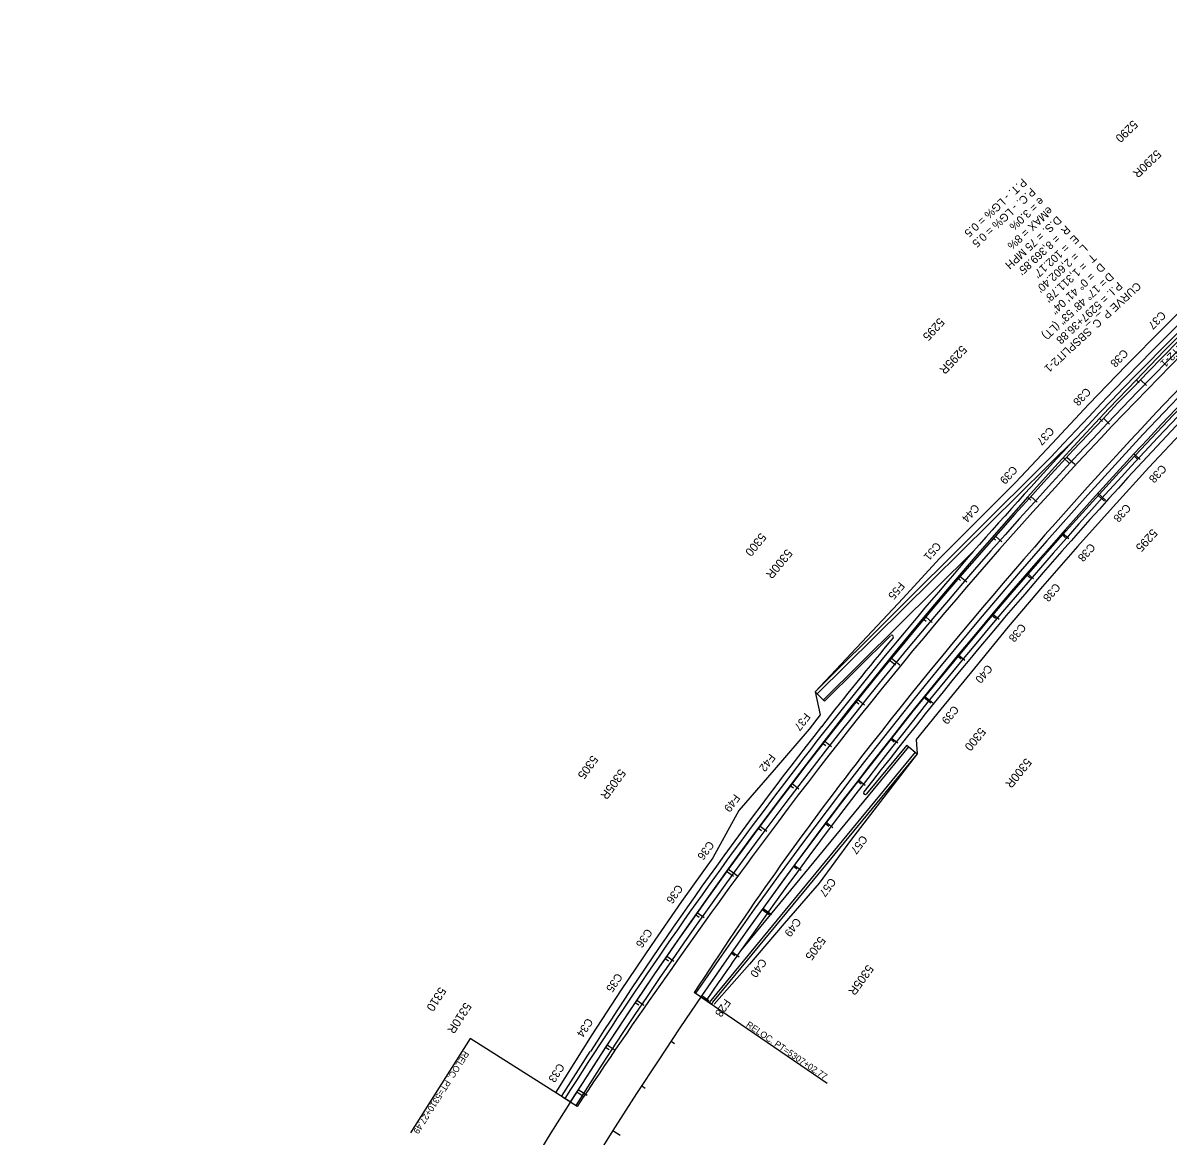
# Model space of a CAD drawing. Extents: x 2160877 to 2175861, y 601747 to 617724.
# Drawn here: x 2161211 to 2163357, y 604108 to 606194 of the extents above; entities that cross this region are included whole.
import ezdxf

# ---------------------------------------------------------------- set-up
doc = ezdxf.new("R2010")
doc.units = 0
for name, color, linetype in [('RD_HC_Cl', 7, 'Continuous'), ('RD_HC_CL_Rel', 7, 'Continuous'), ('RD_HC_Data_Rel', 7, 'Continuous'), ('RD_HC_Data_Tic', 7, 'Continuous'), ('RD_HC_Data_Tic_Rel', 7, 'Continuous'), ('RD_HC_TX_Rel_Sta50', 7, 'Continuous'), ('RD_HC_TX_StaOther', 7, 'Continuous'), ('RD_PD_CstnLmt', 7, 'Continuous'), ('RD_PD_CstnLmt_TX', 7, 'Continuous'), ('RD_PD_Final_LnLine', 7, 'Continuous'), ('RD_PD_Final_TrvlWay', 7, 'Continuous')]:
    doc.layers.add(name, color=color, linetype=linetype)

msp = doc.modelspace()

# ---------------------------------------------------------------- linework, layer by layer
at = {"layer": 'RD_HC_Cl'}
for radius in [8641.9, 8545.9]:
    msp.add_arc((2169535, 599544.7), radius, 132.71947, 164.41949, dxfattribs=at)
at = {"layer": 'RD_HC_CL_Rel'}
for centre, radius, end in [((2169810, 599356.6), 8879.1, 145.62858), ((2169305.2, 599690.4), 8369.8, 147.62243)]:
    msp.add_arc(centre, radius, 129.80773, end, dxfattribs=at)
at = {"layer": 'RD_HC_Data_Rel'}
msp.add_line((2162481.2, 604369.4), (2162717.9, 604207.5), dxfattribs=at)
msp.add_lwpolyline([(2162236.6, 604172.5), (2162048.9, 604291.4), (2161937, 604114.9)], dxfattribs=at)
at = {"layer": 'RD_HC_Data_Tic'}
for p, q in [((2163297.3, 605525.8), (2163303, 605520.3)), ((2163228.5, 605453.3), (2163234.3, 605447.8)), ((2163160.5, 605379.9), (2163172.3, 605369.1)), ((2163293.8, 605382.6), (2163299.6, 605377.1)), ((2163093.4, 605305.7), (2163099.4, 605300.4)), ((2163225.9, 605309.1), (2163237.7, 605298.3)), ((2163027.2, 605230.8), (2163033.2, 605225.6)), ((2163158.9, 605234.9), (2163164.9, 605229.6)), ((2162961.9, 605155.1), (2162967.9, 605149.9)), ((2163092.7, 605159.9), (2163098.8, 605154.7)), ((2162897.4, 605078.7), (2162903.5, 605073.6)), ((2163027.5, 605084.1), (2163033.6, 605079)), ((2162833.8, 605001.5), (2162846.2, 604991.4)), ((2162963.1, 605007.6), (2162969.3, 605002.5)), ((2162771.1, 604923.6), (2162777.4, 604918.6)), ((2162899.6, 604930.3), (2162912.1, 604920.3)), ((2162837.1, 604852.3), (2162843.3, 604847.4)), ((2162709.3, 604845), (2162715.6, 604840.1)), ((2162648.4, 604765.7), (2162654.8, 604760.8)), ((2162775.4, 604773.6), (2162781.8, 604768.7)), ((2162588.5, 604685.6), (2162594.9, 604680.9)), ((2162714.7, 604694.1), (2162721.1, 604689.3)), ((2162654.9, 604614), (2162661.4, 604609.2)), ((2162529.5, 604604.9), (2162542.4, 604595.5)), ((2162596.1, 604533.1), (2162609.1, 604523.8)), ((2162471.4, 604523.5), (2162477.9, 604518.9)), ((2162414.2, 604441.4), (2162420.8, 604436.9)), ((2162538.2, 604451.6), (2162544.7, 604447)), ((2162358.1, 604358.7), (2162364.7, 604354.2)), ((2162481.2, 604369.4), (2162487.8, 604364.9)), ((2162302.8, 604275.3), (2162309.5, 604271)), ((2162425.3, 604286.5), (2162431.9, 604282.1)), ((2162248.6, 604191.3), (2162262.1, 604182.7)), ((2162370.3, 604203), (2162377, 604198.6)), ((2162316.3, 604118.8), (2162329.8, 604110.3))]:
    msp.add_line(p, q, dxfattribs=at)
at = {"layer": 'RD_HC_Data_Tic_Rel'}
for p, q in [((2163305.1, 605525.9), (2163316.6, 605514.8)), ((2163235.8, 605453.8), (2163247.4, 605442.8)), ((2163292.8, 605387), (2163304.6, 605376.1)), ((2163167.4, 605380.9), (2163182.1, 605367.3)), ((2163099.8, 605307.2), (2163111.7, 605296.4)), ((2163225.3, 605313.2), (2163240.2, 605299.8)), ((2163158.7, 605238.7), (2163170.7, 605228.1)), ((2163033.2, 605232.6), (2163045.2, 605222)), ((2162967.4, 605157.3), (2162979.5, 605146.8)), ((2163092.8, 605163.4), (2163104.9, 605152.9)), ((2163027.9, 605087.4), (2163040.1, 605077)), ((2162902.6, 605081.2), (2162914.8, 605070.9)), ((2162838.6, 605004.3), (2162854.1, 604991.6)), ((2162963.8, 605010.6), (2162976.1, 605000.4)), ((2162775.6, 604926.7), (2162788.1, 604916.7)), ((2162900.5, 604933.1), (2162916.1, 604920.6)), ((2162838.2, 604855), (2162850.7, 604845.1)), ((2162713.5, 604848.3), (2162726.1, 604838.4)), ((2162652.3, 604769.2), (2162665.1, 604759.4)), ((2162776.7, 604776.1), (2162789.3, 604766.3)), ((2162592.1, 604689.3), (2162605, 604679.8)), ((2162716.1, 604696.6), (2162728.9, 604686.9)), ((2162656.4, 604616.3), (2162669.3, 604606.9)), ((2162532.9, 604608.7), (2162549.1, 604597)), ((2162474.6, 604527.5), (2162487.7, 604518.2)), ((2162597.6, 604535.4), (2162613.9, 604523.8)), ((2162417.3, 604445.5), (2162430.5, 604436.4)), ((2162539.7, 604453.9), (2162552.8, 604444.7)), ((2162361, 604362.9), (2162374.3, 604354)), ((2162482.8, 604371.7), (2162496, 604362.6)), ((2162305.7, 604279.6), (2162319, 604270.8)), ((2162251.3, 604195.6), (2162268.2, 604184.9))]:
    msp.add_line(p, q, dxfattribs=at)
at = {"layer": 'RD_PD_CstnLmt'}
for p, q in [((2163419.9, 605694.5), (2163348.9, 605623.5)), ((2163348.9, 605623.5), (2163278.1, 605552.2)), ((2163278.1, 605552.2), (2163208.3, 605480)), ((2163208.3, 605480), (2163139.9, 605406.4)), ((2163388.7, 605434), (2163320.6, 605361.3)), ((2163139.9, 605406.4), (2163070.9, 605333.4)), ((2163320.6, 605361.3), (2163253.7, 605287.5)), ((2163070.9, 605333.4), (2162999.9, 605262)), ((2163253.7, 605287.5), (2163187, 605213.6)), ((2162999.9, 605262), (2162928.5, 605190.9)), ((2163187, 605213.6), (2163121.5, 605138.6)), ((2162928.5, 605190.9), (2162860.7, 605116.4)), ((2163121.5, 605138.6), (2163057.1, 605062.7)), ((2162860.7, 605116.4), (2162695.3, 604940.8)), ((2163057.1, 605062.7), (2162994.2, 604985.4)), ((2162994.2, 604985.4), (2162930.9, 604908.6)), ((2162684.3, 604871.1), (2162618.9, 604794.7)), ((2162886.8, 604824.9), (2162761.6, 604662.3)), ((2162618.9, 604794.7), (2162552.6, 604718.7)), ((2162552.6, 604718.7), (2162503.6, 604630)), ((2162761.6, 604662.3), (2162702.7, 604582.3)), ((2162503.6, 604630), (2162445.2, 604548.3)), ((2162702.7, 604582.3), (2162637.1, 604507.1)), ((2162445.2, 604548.3), (2162388, 604465.8)), ((2162637.1, 604507.1), (2162572.7, 604430.8)), ((2162388, 604465.8), (2162332.1, 604382.3)), ((2162572.7, 604430.8), (2162505.9, 604355.8)), ((2162332.1, 604382.3), (2162277.1, 604298.3)), ((2162277.1, 604298.3), (2162209.5, 604191))]:
    msp.add_line(p, q, dxfattribs=at)
for points in [[(2162695.3, 604940.8), (2162705.1, 604897.6), (2162684.3, 604871.1)], [(2162930.9, 604908.6), (2162884.8, 604851.6), (2162886.8, 604824.9)]]:
    msp.add_lwpolyline(points, dxfattribs=at)
at = {"layer": 'RD_PD_Final_LnLine'}
for p, q in [((2162699.5, 604937), (2163184.6, 605417)), ((2162695.3, 604940.8), (2163137.8, 605381.3)), ((2162710.7, 604925.6), (2162991.9, 605203.8)), ((2162712.8, 604923.5), (2162836.9, 605046.2)), ((2162501, 604355.8), (2162469, 604377.5)), ((2162249.4, 604164.1), (2162220.2, 604182.8))]:
    msp.add_line(p, q, dxfattribs=at)
for points in [[(2162882.9, 604828), (2162670.6, 604569.9), (2162496.6, 604358.9)], [(2162870.6, 604838.2), (2162658.3, 604580.1), (2162555.5, 604455.4)]]:
    msp.add_lwpolyline(points, dxfattribs=at)
for centre, radius, start, end in [((2169810, 599356.6), 8891.1, 129.80773, 145.62858), ((2169810, 599356.6), 8867.1, 129.80773, 144.89859), ((2169305.2, 599690.4), 8381.8, 129.80773, 136.90521), ((2169305.2, 599690.4), 8357.8, 129.80773, 147.62243), ((2169305.2, 599690.4), 8381.8, 136.90521, 138.86967), ((2169305.2, 599690.4), 8381.8, 138.86967, 147.62243), ((2169810, 599356.6), 8867.1, 144.89859, 145.62858), ((2169810, 599356.6), 8855.1, 145.60256, 145.62858)]:
    msp.add_arc(centre, radius, start, end, dxfattribs=at)
at = {"layer": 'RD_PD_Final_TrvlWay'}
for p, q in [((2162695.3, 604940.8), (2162712.8, 604923.5)), ((2162695.3, 604940.8), (2162712.8, 604923.5)), ((2162867.2, 604840.9), (2162791.7, 604749.7)), ((2162220.2, 604182.8), (2162274.1, 604266.9))]:
    msp.add_line(p, q, dxfattribs=at)
for points in [[(2162867.2, 604840.9), (2162886.8, 604824.9)], [(2162867.2, 604840.9), (2162886.8, 604824.9)], [(2162886.8, 604824.9), (2162674.5, 604566.7), (2162503.3, 604359.2)]]:
    msp.add_lwpolyline(points, dxfattribs=at)
for centre, radius, start, end in [((2169810, 599356.6), 8901.1, 129.80773, 142.13894), ((2169305.2, 599690.4), 8391.8, 129.80773, 137.30123), ((2169305.2, 599690.4), 8347.8, 129.80773, 143.57306), ((2169810, 599356.6), 8857.1, 131.47407, 142.45996), ((2169305.2, 599690.4), 8391.8, 140.37636, 141.83733), ((2162839.1, 605044.1), 3, 320.3767, 134.6957), ((2168840.4, 600055.8), 7800.6, 141.83733, 147.32681), ((2167652.2, 601034.1), 6168, 142.13894, 147.17611), ((2162789.3, 604751.6), 3, 142.46, 320.3646), ((2172511.3, 597324.3), 12332.5, 143.57306, 146.31587)]:
    msp.add_arc(centre, radius, start, end, dxfattribs=at)

# ---------------------------------------------------------------- texts
at = {"layer": 'RD_HC_Data_Rel'}
for s, height, rotation, p in [('P.T. - LG% = 0.5', 15, 222.7195, (2163083.9, 605904.2)), ('P.C. - LG% = 0.5', 15, 222.7195, (2163100.2, 605886.6)), ('e = 3.0%', 15, 222.7195, (2163116.5, 605869)), ('eMAX = 8%', 15, 222.7195, (2163132.7, 605851.3)), ('D.S. = 75 MPH', 15, 222.7195, (2163149, 605833.7)), ("R  = 8,369.85'", 15, 222.7195, (2163165.3, 605816.1)), ("E  = 102.17'", 15, 222.7195, (2163181.6, 605798.4)), ("L  = 2,602.40'", 15, 222.7195, (2163197.9, 605780.8)), ("T  = 1,311.78'", 15, 222.7195, (2163214.1, 605763.2)), ('D  = 0%%d 41\' 04"', 15, 222.7195, (2163230.4, 605745.5)), ('   = 17%%d 48\' 53" (LT)', 15, 222.7195, (2163246.7, 605727.9)), ('P.I. = 5297+36.88', 15, 222.7195, (2163263, 605710.3)), ('D ', 15, 222.7195, (2163246.7, 605727.9)), ('CURVE P_C_SBSPLIT2-1', 15, 222.7195, (2163298, 605710)), ('P C SBSPLIT2-1', 15, 224.5304, (2163448.1, 605663.6)), ('RELOC. PT=5307+02.77', 12, 325.6286, (2162564.9, 604314.6)), ('RELOC. PT=5310+27.49', 12, 237.6224, (2162037.5, 604269.1))]:
    msp.add_text(s, height=height, rotation=rotation, dxfattribs=at).set_placement(p)
at = {"layer": 'RD_HC_TX_Rel_Sta50'}
for s, rotation, p in [('5290R', 223.7432, (2163335, 605957.8)), ('5295R', 227.166, (2162969.9, 605591.5)), ('5300R', 230.5887, (2162642.1, 605209.9)), ('5300R', 231.0937, (2163090.4, 604818.1)), ('5305R', 234.0115, (2162329.1, 604797.8)), ('5305R', 234.3201, (2162793.5, 604431)), ('5310R', 237.4342, (2162039.1, 604360.3))]:
    msp.add_text(s, height=16, rotation=rotation, dxfattribs=at).set_placement(p)
at = {"layer": 'RD_HC_TX_StaOther'}
for s, rotation, p in [('5290', 224.2142, (2163290.9, 606013.4)), ('5295', 227.5292, (2162927.9, 605643)), ('5300', 230.8442, (2162593.1, 605240.1)), ('5295', 227.5832, (2163327, 605247.7)), ('5300', 230.9354, (2163004.4, 604875.4)), ('5305', 234.1592, (2162277.2, 604823.4)), ('5305', 234.2877, (2162703.6, 604484)), ('5310', 237.4741, (2161991.7, 604389.2))]:
    msp.add_text(s, height=16, rotation=rotation, dxfattribs=at).set_placement(p)
at = {"layer": 'RD_PD_CstnLmt_TX'}
for s, rotation, p in [('C37', 225.1123, (2163343.9, 605655.5)), ('C38', 225.7969, (2163273, 605584.4)), ('C38', 226.4814, (2163203, 605512.2)), ('C37', 227.166, (2163134.2, 605438.6)), ('C38', 227.222, (2163344.6, 605368)), ('C39', 227.8505, (2163065.1, 605365.8)), ('C44', 228.5351, (2162993.7, 605294.2)), ('C38', 227.8673, (2163277.7, 605294.5)), ('C51', 229.2196, (2162921.7, 605222.9)), ('C38', 228.5125, (2163210.9, 605220.7)), ('F55', 229.9042, (2162853.4, 605148.2)), ('C38', 229.1578, (2163145.3, 605145.9)), ('C38', 229.8031, (2163080.8, 605070.3)), ('C40', 230.4484, (2163017.9, 604993.3)), ('C39', 231.0937, (2162954.5, 604916.6)), ('F37', 231.9578, (2162676.2, 604902.8)), ('F42', 232.6424, (2162610.5, 604826.3)), ('F49', 233.3269, (2162544.2, 604750.6)), ('C36', 234.0115, (2162495.4, 604662.8)), ('C57', 233.0295, (2162783, 604673.5)), ('C36', 234.696, (2162436.8, 604581.1)), ('C57', 233.6748, (2162723.9, 604593.7)), ('C49', 234.3201, (2162658.4, 604518.8)), ('C36', 235.3806, (2162379.4, 604498.5)), ('C40', 234.9654, (2162593.8, 604442.7)), ('C35', 236.0651, (2162323.3, 604415.2)), ('F28', 235.6107, (2162526.3, 604367)), ('C34', 236.7497, (2162267.9, 604331)), ('C33', 237.4342, (2162214.3, 604246.3))]:
    msp.add_text(s, height=15, rotation=rotation, dxfattribs=at).set_placement(p)

doc.saveas('drawing.dxf')
